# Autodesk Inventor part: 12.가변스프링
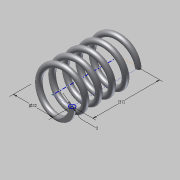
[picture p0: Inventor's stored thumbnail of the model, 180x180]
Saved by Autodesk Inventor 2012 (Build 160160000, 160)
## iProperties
Created: 2014-12
Part Number: 12.가변스프링
Material: Default
Document SubType Name: Modeling
Designer: HOME
Density: 1 g/cm^3
Mass: 2.40525 g
Surface Area: 32.6126 cm^2
Volume: 2.40525 cm^3
Author: HOME
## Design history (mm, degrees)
sketch "스케치1"
  geometry: L1 (0, 0)-(11, 0); L2 (11, 0)-(11, 36.411); L3 (11, 36.411)-(0, 36.411); L4 (0, 36.411)-(0, 0); C1 r 1.5 at (11, 0); 1 further point
  constraints: 8 end point, 2 coincident, 2 parallel, 1 centre point, 1 horizontal, 1 perpendicular
  dimensions: "d0" = 22 diameter of L2 L4; "d1" = 36.4112 distance of L1.end L2.end (derived); "d2" = 3 diameter of C1
feature "코일1" pitch "d3" = 10; turns "d5" = 5; dims "d4" = 36.4112 (= d1), "d6" = 0, angle "d7" = 90 deg, angle "d8" = 90 deg, "d9" = 0, "d10" = 0
sketch "스케치2"
  geometry: L1 (-12.5, 0)-(-9.5, 0) reference; 1 further point
  constraints: 1 horizontal alignment
extrude "돌출1" cut sketch "스케치2" stored distance "d11" = 10; taper "d12" = 0 deg
node "작업 평면1"
sketch "스케치3"
  geometry: L1 (-9.5, 0)-(-12.5, 0) reference; 1 further point
  constraints: 1 horizontal alignment
extrude "돌출2" cut sketch "스케치3" stored distance "d13" = 10; taper "d14" = 0 deg
node "솔리드1"
node "절단 모서리 투영1"
node "절단 모서리 투영2"
